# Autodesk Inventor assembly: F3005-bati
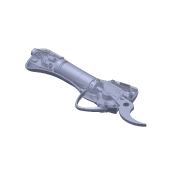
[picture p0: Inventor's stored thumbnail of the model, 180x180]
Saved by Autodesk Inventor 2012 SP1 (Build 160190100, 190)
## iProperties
Created: 2014-12
Part Number: F3005-bati
Document SubType Name: Assembly
Designer: Bruno
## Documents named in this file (22)
- D:\Cours\Systèmes\secateur-hydrogene-Pragma\Documentation\Dossier technique Infaco F3005\Solidworks\Composants importés\F3005-bati.iam
- D:\Cours\Systèmes\secateur-hydrogene-Pragma\Documentation\Dossier technique Infaco F3005\Solidworks\Composants importés\F3005\Tête sécateur.ipt
- D:\Cours\Systèmes\secateur-hydrogene-Pragma\Documentation\Dossier technique Infaco F3005\Solidworks\Composants importés\F3005\Crochet.ipt
- D:\Cours\Systèmes\secateur-hydrogene-Pragma\Documentation\Dossier technique Infaco F3005\Solidworks\Composants importés\F3005\Vis moteur.ipt
- D:\Cours\Systèmes\secateur-hydrogene-Pragma\Documentation\Dossier technique Infaco F3005\Solidworks\Composants importés\F3005\Vis lame M5x10.ipt
- D:\Cours\Systèmes\secateur-hydrogene-Pragma\Documentation\Dossier technique Infaco F3005\Solidworks\Composants importés\F3005\Vis gachette.ipt
- D:\Cours\Systèmes\secateur-hydrogene-Pragma\Documentation\Dossier technique Infaco F3005\Solidworks\Composants importés\F3005\Protection gachette.ipt
- D:\Cours\Systèmes\secateur-hydrogene-Pragma\Documentation\Dossier technique Infaco F3005\Solidworks\Composants importés\F3005\Bouton interrupteur.ipt
- D:\Cours\Systèmes\secateur-hydrogene-Pragma\Documentation\Dossier technique Infaco F3005\Solidworks\Composants importés\F3005\Vis tête.ipt
- D:\Cours\Systèmes\secateur-hydrogene-Pragma\Documentation\Dossier technique Infaco F3005\Solidworks\Composants importés\F3005\vis tête-2.ipt
- D:\Cours\Systèmes\secateur-hydrogene-Pragma\Documentation\Dossier technique Infaco F3005\Solidworks\Composants importés\F3005\Etiquette droite.ipt
- D:\Cours\Systèmes\secateur-hydrogene-Pragma\Documentation\Dossier technique Infaco F3005\Solidworks\Composants importés\F3005\Etiquette gauche.ipt
- D:\Cours\Systèmes\secateur-hydrogene-Pragma\Documentation\Dossier technique Infaco F3005\Solidworks\Composants importés\F3005\Vis carter 3x16.ipt
- D:\Cours\Systèmes\secateur-hydrogene-Pragma\Documentation\Dossier technique Infaco F3005\Solidworks\Composants importés\F3005\Vis carter 3x20.ipt
- D:\Cours\Systèmes\secateur-hydrogene-Pragma\Documentation\Dossier technique Infaco F3005\Solidworks\Composants importés\F3005\Vis carter 3x12.ipt
- D:\Cours\Systèmes\secateur-hydrogene-Pragma\Documentation\Dossier technique Infaco F3005\Solidworks\Composants importés\F3005\LED complète.iam
- D:\Cours\Systèmes\secateur-hydrogene-Pragma\Documentation\Dossier technique Infaco F3005\Solidworks\Composants importés\F3005\Carte électrotique + connecteur.iam
- D:\Cours\Systèmes\secateur-hydrogene-Pragma\Documentation\Dossier technique Infaco F3005\Solidworks\Composants importés\F3005\Rondelle.ipt
- D:\Cours\Systèmes\secateur-hydrogene-Pragma\Documentation\Dossier technique Infaco F3005\Solidworks\Composants importés\F3005\Roulement tête.ipt
- D:\Cours\Systèmes\secateur-hydrogene-Pragma\Documentation\Dossier technique Infaco F3005\Solidworks\Composants importés\F3005\Motoréducteur.iam
- D:\Cours\Systèmes\secateur-hydrogene-Pragma\Documentation\Dossier technique Infaco F3005\Solidworks\Composants importés\F3005\Carter gauche.ipt
- D:\Cours\Systèmes\secateur-hydrogene-Pragma\Documentation\Dossier technique Infaco F3005\Solidworks\Composants importés\F3005\Carter droit.ipt
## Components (29 placed, 21 different names)
1. Tête sécateur:1
2. Crochet:1
3. Vis moteur:1
4. Vis moteur:2
5. Vis moteur:3
6. Vis moteur:4
7. Vis moteur:5
8. Vis lame M5x10:1
9. Vis gachette:1
10. Protection gachette:1
11. Bouton interrupteur:1
12. Vis tête:1
13. vis tête-2:1
14. Vis tête:2
15. Etiquette droite:1
16. Etiquette gauche:1
17. Vis carter 3x16:1
18. Vis carter 3x16:2
19. Vis carter 3x16:3
20. Vis carter 3x16:4
21. Vis carter 3x20:1
22. Vis carter 3x12:1
23. LED complète:1 [sub-assembly]
24. Carte électrotique + connecteur:1 [sub-assembly]
25. Rondelle:1
26. Roulement tête:1
27. Motoréducteur:1 [sub-assembly]
28. Carter gauche:1
29. Carter droit:1
